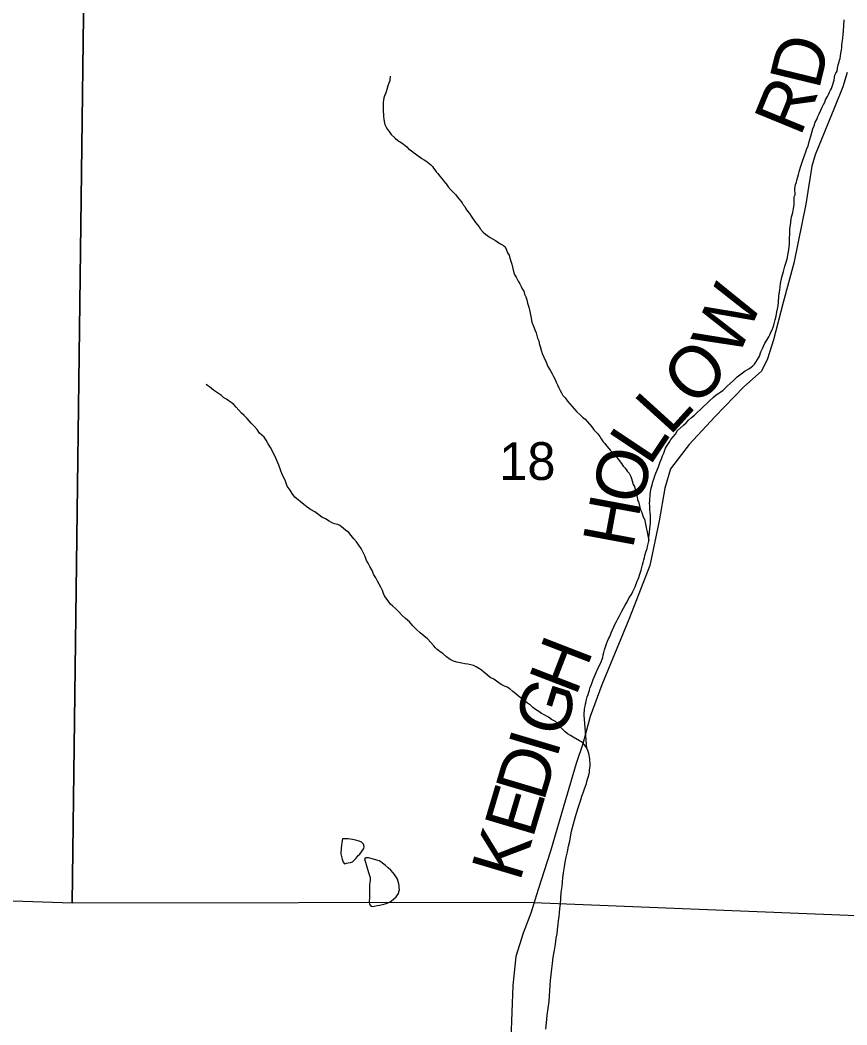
# Model space of a CAD drawing. Extents: x -14196 to 143, y -6096 to 28.
# Drawn here: x 59.148 to 60.064, y 19.711 to 20.825 of the extents above; entities that cross this region are included whole.
import ezdxf

# ---------------------------------------------------------------- set-up
doc = ezdxf.new("R2010")
doc.units = 0
for name, color, linetype in [('GM_X_Corporation', 7, 'Continuous'), ('GM_X_County_Road', 7, 'Continuous'), ('GM_X_County_Road_Text', 7, 'Continuous'), ('GM_X_Minor_Lake', 7, 'Continuous'), ('GM_X_Minor_River', 7, 'Continuous'), ('GM_X_Section_Text', 7, 'Continuous')]:
    doc.layers.add(name, color=color, linetype=linetype)

msp = doc.modelspace()

# ---------------------------------------------------------------- linework, layer by layer
at = {"layer": 'GM_X_Corporation'}
for points in [[(59.2185, 20.859), (59.2056, 19.8463), (58.2013, 19.8806), (58.2134, 20.8668)], [(60.2211, 20.8437), (60.2036, 19.8271), (59.7077, 19.847), (59.2056, 19.8463), (59.2185, 20.859)]]:
    msp.add_lwpolyline(points, close=True, dxfattribs=at)
at = {"layer": 'GM_X_County_Road'}
msp.add_lwpolyline([(60.0646, 20.767), (60.0597, 20.7513), (60.0504, 20.7283), (60.0293, 20.6757), (60.0255, 20.6634), (60.0189, 20.621), (60.0054, 20.5557), (59.9936, 20.5121), (59.9829, 20.4707), (59.9762, 20.4497), (59.9697, 20.4362), (59.95, 20.4186), (59.9178, 20.3855), (59.8893, 20.3547), (59.8687, 20.328), (59.8624, 20.3065), (59.8561, 20.2703), (59.846, 20.2206), (59.8235, 20.1626), (59.7928, 20.0885), (59.7796, 20.0532), (59.7716, 20.0229), (59.7642, 20.0011), (59.7523, 19.9609), (59.7359, 19.9042), (59.7222, 19.8617), (59.7141, 19.8352), (59.7055, 19.8133), (59.6974, 19.7873), (59.6941, 19.7553), (59.6906, 19.6666)], dxfattribs=at)
at = {"layer": 'GM_X_Minor_Lake'}
for points in [[(59.5048, 19.916), (59.5038, 19.9076), (59.5038, 19.9057), (59.5035, 19.9034), (59.5035, 19.9011), (59.5039, 19.8981), (59.5047, 19.8951), (59.5059, 19.892), (59.5074, 19.8902), (59.5097, 19.8906), (59.5116, 19.891), (59.5142, 19.8914), (59.5161, 19.8922), (59.5184, 19.8945), (59.5203, 19.8964), (59.5225, 19.8991), (59.5244, 19.9006), (59.5289, 19.9071), (59.5292, 19.9094), (59.5284, 19.9117), (59.5261, 19.9139), (59.5235, 19.915), (59.5212, 19.9158), (59.5181, 19.9165), (59.5162, 19.9169), (59.5136, 19.9172), (59.5113, 19.9176), (59.5079, 19.9179), (59.506, 19.9179), (59.5052, 19.9179), (59.5048, 19.916)], [(59.5048, 19.916), (59.5038, 19.9076), (59.5038, 19.9057), (59.5035, 19.9034), (59.5035, 19.9011), (59.5039, 19.8981), (59.5047, 19.8951), (59.5059, 19.892), (59.5074, 19.8902), (59.5097, 19.8906), (59.5116, 19.891), (59.5142, 19.8914), (59.5161, 19.8922), (59.5184, 19.8945), (59.5203, 19.8964), (59.5225, 19.8991)], [(59.5225, 19.8991), (59.5244, 19.9006), (59.5289, 19.9071), (59.5292, 19.9094), (59.5284, 19.9117), (59.5261, 19.9139), (59.5235, 19.915), (59.5212, 19.9158), (59.5181, 19.9165), (59.5162, 19.9169), (59.5136, 19.9172), (59.5113, 19.9176), (59.5079, 19.9179), (59.506, 19.9179), (59.5052, 19.9179), (59.5048, 19.916)], [(59.5566, 19.847), (59.5592, 19.8485), (59.5622, 19.8512), (59.5648, 19.8535), (59.5671, 19.857), (59.5678, 19.8589), (59.5682, 19.8615), (59.5681, 19.8634), (59.5681, 19.8653), (59.5677, 19.868), (59.5661, 19.8729), (59.565, 19.8748), (59.563, 19.8782), (59.5615, 19.8801), (59.5588, 19.8831), (59.5557, 19.8857), (59.5526, 19.8884), (59.5496, 19.8906), (59.5477, 19.8921), (59.5458, 19.8932), (59.5431, 19.894), (59.5397, 19.8951), (59.5339, 19.8965), (59.5313, 19.8965), (59.5294, 19.8957)], [(59.5294, 19.8957), (59.5341, 19.8806), (59.5353, 19.8772), (59.5357, 19.8749), (59.5358, 19.8718), (59.5354, 19.8692), (59.535, 19.8673), (59.5351, 19.8654), (59.5351, 19.8627), (59.5351, 19.8604), (59.5352, 19.8585), (59.5352, 19.8551), (59.5352, 19.8532), (59.5352, 19.8513), (59.5349, 19.8494), (59.5349, 19.8475), (59.5353, 19.8452), (59.5369, 19.8426), (59.5403, 19.843), (59.5437, 19.8438), (59.5463, 19.8442), (59.5494, 19.845), (59.5524, 19.8458), (59.5547, 19.8466), (59.5566, 19.847), (59.5592, 19.8485), (59.5622, 19.8512), (59.5648, 19.8535), (59.5671, 19.857), (59.5678, 19.8589), (59.5682, 19.8615), (59.5681, 19.8634), (59.5681, 19.8653), (59.5677, 19.868), (59.5661, 19.8729), (59.565, 19.8748), (59.563, 19.8782), (59.5615, 19.8801), (59.5588, 19.8831), (59.5557, 19.8857), (59.5526, 19.8884), (59.5496, 19.8906), (59.5477, 19.8921), (59.5458, 19.8932), (59.5431, 19.894), (59.5397, 19.8951), (59.5339, 19.8965), (59.5313, 19.8965), (59.5294, 19.8957)], [(59.5294, 19.8957), (59.5341, 19.8806), (59.5353, 19.8772), (59.5357, 19.8749), (59.5358, 19.8718), (59.5354, 19.8692), (59.535, 19.8673), (59.5351, 19.8654), (59.5351, 19.8627), (59.5351, 19.8604), (59.5352, 19.8585), (59.5352, 19.8551), (59.5352, 19.8532), (59.5352, 19.8513), (59.5349, 19.8494), (59.5349, 19.8475), (59.5353, 19.8452), (59.5369, 19.8426), (59.5403, 19.843), (59.5437, 19.8438), (59.5463, 19.8442), (59.5494, 19.845), (59.5524, 19.8458), (59.5547, 19.8466), (59.5566, 19.847)]]:
    msp.add_lwpolyline(points, dxfattribs=at)
at = {"layer": 'GM_X_Minor_River'}
for points in [[(60.0293, 20.7119), (60.0308, 20.7149), (60.0319, 20.7184), (60.0334, 20.7214), (60.0353, 20.7252), (60.0367, 20.7287), (60.0382, 20.7317), (60.0397, 20.7344), (60.0404, 20.7367), (60.0416, 20.7386), (60.0427, 20.7405), (60.0438, 20.7428), (60.0449, 20.7455), (60.046, 20.7474), (60.0471, 20.7493), (60.0479, 20.7516), (60.0486, 20.7539), (60.0493, 20.7565), (60.0501, 20.7588), (60.0504, 20.7615), (60.0511, 20.7642), (60.0522, 20.7665), (60.0534, 20.7687), (60.0537, 20.7718), (60.0541, 20.7737), (60.0548, 20.7756), (60.0559, 20.779), (60.0562, 20.7809), (60.057, 20.7828), (60.0573, 20.7855), (60.0577, 20.7886), (60.0584, 20.792), (60.0587, 20.795), (60.0587, 20.7977), (60.0591, 20.8003), (60.0594, 20.8026), (60.0598, 20.8053), (60.0601, 20.8095), (60.0604, 20.8129), (60.0614, 20.8255)], [(59.558, 20.763), (59.5582, 20.7625), (59.5578, 20.7602), (59.5575, 20.7579), (59.5567, 20.7553), (59.5556, 20.7522), (59.5545, 20.7484), (59.5531, 20.7446), (59.5516, 20.7412), (59.5509, 20.7389), (59.5505, 20.7366), (59.5502, 20.7343), (59.5502, 20.7309), (59.5502, 20.7271), (59.5503, 20.7237), (59.5507, 20.721), (59.5507, 20.7184), (59.5511, 20.7153), (59.5515, 20.7127), (59.552, 20.7096), (59.5535, 20.7066), (59.5551, 20.704), (59.557, 20.7017), (59.5593, 20.6983), (59.5635, 20.6945), (59.5666, 20.6919), (59.5701, 20.6897), (59.5727, 20.6878), (59.5747, 20.6863), (59.5766, 20.6848), (59.5785, 20.6825), (59.5812, 20.6807), (59.5835, 20.6788), (59.5862, 20.6769), (59.5931, 20.6717), (59.5957, 20.6702), (59.5988, 20.6683), (59.6011, 20.6664), (59.603, 20.6649), (59.6049, 20.6631), (59.6061, 20.6612), (59.6076, 20.6593), (59.6092, 20.657), (59.6107, 20.6551), (59.6127, 20.6525), (59.6154, 20.6495), (59.6177, 20.6468), (59.62, 20.6438), (59.6223, 20.6404), (59.6254, 20.637), (59.6281, 20.634), (59.6308, 20.6314), (59.6327, 20.6288), (59.6346, 20.6269), (59.6362, 20.6246), (59.6377, 20.6227), (59.6389, 20.6205), (59.6408, 20.6186), (59.642, 20.6159), (59.6439, 20.6133), (59.6458, 20.6107), (59.6478, 20.608), (59.6493, 20.6058), (59.6512, 20.6031), (59.6528, 20.6008), (59.6547, 20.5982), (59.6566, 20.5959), (59.6582, 20.5933), (59.6613, 20.5903), (59.6636, 20.588), (59.6662, 20.5862), (59.6689, 20.5843), (59.6716, 20.5828), (59.6747, 20.5809), (59.6773, 20.5791), (59.6804, 20.5772), (59.6835, 20.5753), (59.6854, 20.5738), (59.6866, 20.5712), (59.6881, 20.5674), (59.69, 20.5648), (59.6908, 20.5613), (59.6916, 20.5579), (59.6928, 20.5545), (59.6952, 20.545), (59.6964, 20.5424), (59.6976, 20.5401), (59.6987, 20.5382), (59.6999, 20.536), (59.7018, 20.5329), (59.7034, 20.5299), (59.7045, 20.5273), (59.7061, 20.5246), (59.7069, 20.5216), (59.7084, 20.5186), (59.7096, 20.5152), (59.7104, 20.5114), (59.7116, 20.5072), (59.7128, 20.5023)], [(59.8624, 20.3484), (59.8631, 20.3507), (59.8642, 20.3526), (59.8657, 20.3549), (59.8672, 20.3572), (59.8691, 20.3602), (59.8717, 20.3633), (59.8743, 20.3664), (59.8766, 20.3702), (59.88, 20.3733), (59.883, 20.3763), (59.886, 20.379), (59.8886, 20.3817), (59.892, 20.3848), (59.8954, 20.3875), (59.9055, 20.3971), (59.9089, 20.4002), (59.9119, 20.4032), (59.9164, 20.4071), (59.9194, 20.4098), (59.9224, 20.4117), (59.9247, 20.4133), (59.9273, 20.4152), (59.9292, 20.4171), (59.9314, 20.4194), (59.9348, 20.4225), (59.9386, 20.4259), (59.9427, 20.4298), (59.9472, 20.4332), (59.9517, 20.4363), (59.9555, 20.4386), (59.9581, 20.4406), (59.96, 20.4421), (59.9619, 20.444), (59.9634, 20.4459), (59.9653, 20.449), (59.9675, 20.4528), (59.969, 20.4574), (59.9712, 20.462), (59.9734, 20.467), (59.9756, 20.4704), (59.9779, 20.4742), (59.979, 20.4765), (59.9801, 20.4792), (59.9816, 20.4819), (59.9827, 20.4849), (59.9838, 20.4887), (59.9849, 20.4929), (59.986, 20.4971), (59.9867, 20.5017), (59.9877, 20.5066), (59.9884, 20.5119), (59.9887, 20.5196), (59.9898, 20.526), (59.9908, 20.5333), (59.9923, 20.5401), (59.9941, 20.5466), (59.9956, 20.5523), (59.997, 20.5569), (59.9985, 20.5622), (59.9992, 20.5668), (59.9999, 20.5706), (60.0002, 20.574), (60.0006, 20.5774), (60.0005, 20.5809), (60.0012, 20.5904), (60.0011, 20.5942), (60.0018, 20.598), (60.0022, 20.6014), (60.0025, 20.6044), (60.0029, 20.6071), (60.0036, 20.6094), (60.0043, 20.6121), (60.005, 20.6162), (60.0058, 20.6204), (60.0057, 20.6239), (60.0057, 20.6269), (60.006, 20.6292), (60.0068, 20.6315), (60.0067, 20.6383), (60.0074, 20.6429), (60.0085, 20.6455), (60.0088, 20.6478), (60.0099, 20.6513), (60.0107, 20.6539), (60.0114, 20.657), (60.0121, 20.6596), (60.0128, 20.6623), (60.0139, 20.6657), (60.015, 20.6688), (60.0176, 20.6764), (60.0187, 20.6791), (60.0198, 20.6829), (60.0213, 20.6856), (60.022, 20.689), (60.0231, 20.6928), (60.0242, 20.6966), (60.0253, 20.7008), (60.0264, 20.7046), (60.0279, 20.7081), (60.0293, 20.7119)], [(59.7128, 20.5023), (59.714, 20.4966), (59.7152, 20.4905), (59.7168, 20.486), (59.7184, 20.4818), (59.7199, 20.4784), (59.7207, 20.4758), (59.7215, 20.4727), (59.7227, 20.4697), (59.7231, 20.4667), (59.7243, 20.4633), (59.7255, 20.4595), (59.7267, 20.4557), (59.7282, 20.4515), (59.731, 20.4462), (59.7329, 20.4413), (59.7352, 20.4371), (59.7372, 20.4337), (59.7391, 20.43), (59.7411, 20.4269), (59.7422, 20.4239), (59.7434, 20.4209), (59.745, 20.4175), (59.7465, 20.4148), (59.7481, 20.4122), (59.7496, 20.4092), (59.7516, 20.4069), (59.7531, 20.405), (59.7546, 20.4028), (59.757, 20.3997), (59.7597, 20.3971), (59.7623, 20.3941), (59.765, 20.3911), (59.7681, 20.3881), (59.7712, 20.3851), (59.7743, 20.3828), (59.7816, 20.3742), (59.7839, 20.3711), (59.7862, 20.3685), (59.7881, 20.3666), (59.7904, 20.3636), (59.792, 20.361), (59.7943, 20.3579), (59.7955, 20.3561), (59.7982, 20.353), (59.8005, 20.3504), (59.802, 20.3485), (59.8055, 20.3451), (59.8066, 20.3433), (59.8086, 20.3414), (59.8101, 20.3395), (59.812, 20.3372), (59.8143, 20.3338), (59.8163, 20.3308), (59.8182, 20.3289), (59.8197, 20.327), (59.8209, 20.3252), (59.8228, 20.3229), (59.8248, 20.3195), (59.8256, 20.3172), (59.8263, 20.3146), (59.8275, 20.3104), (59.8287, 20.3081), (59.8295, 20.3051), (59.8303, 20.3025), (59.8311, 20.2994), (59.8319, 20.2964), (59.8323, 20.2937), (59.8335, 20.2903), (59.8343, 20.2869), (59.8351, 20.2839), (59.8359, 20.2816), (59.837, 20.2793), (59.8382, 20.2759), (59.839, 20.2737), (59.8398, 20.2721), (59.8447, 20.2485)], [(59.5871, 20.1498), (59.5833, 20.1539), (59.5794, 20.1581), (59.5752, 20.1618), (59.5714, 20.1652), (59.5679, 20.169), (59.5644, 20.1728), (59.561, 20.1758), (59.5583, 20.178), (59.5564, 20.1806), (59.5548, 20.1829), (59.5533, 20.1848), (59.5517, 20.1871), (59.5506, 20.1897), (59.5494, 20.1931), (59.5478, 20.1965), (59.5459, 20.1999), (59.544, 20.2033), (59.542, 20.2071), (59.5401, 20.2105), (59.5381, 20.215), (59.5354, 20.2196), (59.5335, 20.2234), (59.5319, 20.2264), (59.5303, 20.2305), (59.528, 20.2351), (59.5257, 20.2396), (59.5233, 20.2434), (59.5206, 20.2468), (59.5179, 20.2502), (59.5149, 20.2539), (59.5122, 20.2573), (59.5087, 20.26), (59.5064, 20.2618), (59.5041, 20.2637), (59.5022, 20.2652), (59.4999, 20.2663), (59.4965, 20.267), (59.493, 20.2685), (59.4904, 20.27), (59.4862, 20.2723), (59.4823, 20.2741), (59.4789, 20.2767), (59.4747, 20.2801), (59.4697, 20.2827), (59.4662, 20.2854), (59.4624, 20.2884), (59.4524, 20.2966), (59.4494, 20.3004), (59.447, 20.3042), (59.4439, 20.3087), (59.4416, 20.3151), (59.4385, 20.3215), (59.4345, 20.3318), (59.4314, 20.3397), (59.4283, 20.3461), (59.4252, 20.3514), (59.4229, 20.3556), (59.4205, 20.3597), (59.4182, 20.3628), (59.4159, 20.365), (59.4132, 20.3673), (59.4105, 20.3714), (59.4074, 20.3752), (59.404, 20.3786), (59.3994, 20.3835), (59.3963, 20.3868), (59.3932, 20.3895), (59.3901, 20.3929), (59.3874, 20.3963), (59.3847, 20.3993), (59.3817, 20.4015), (59.3794, 20.403), (59.3767, 20.4049), (59.3736, 20.4067), (59.371, 20.409), (59.3667, 20.412), (59.3621, 20.415), (59.3579, 20.4187), (59.3556, 20.4202), (59.3541, 20.4214)], [(59.7761, 20.0179), (59.7729, 20.0548), (59.7732, 20.0575), (59.7736, 20.0598), (59.7735, 20.0617), (59.7743, 20.0647), (59.7746, 20.0674), (59.7753, 20.0701), (59.7757, 20.072), (59.7764, 20.075), (59.7775, 20.0777), (59.7782, 20.0803), (59.779, 20.0826), (59.7797, 20.0853), (59.7808, 20.088), (59.7819, 20.091), (59.783, 20.0945), (59.7886, 20.1071), (59.7904, 20.1105), (59.7919, 20.1139), (59.793, 20.117), (59.7937, 20.1189), (59.7941, 20.1216), (59.7948, 20.1242), (59.7955, 20.1273), (59.7966, 20.1307), (59.7977, 20.1338), (59.7988, 20.1368), (59.7999, 20.1395), (59.8011, 20.1414), (59.8022, 20.1437), (59.8029, 20.146), (59.8044, 20.1494), (59.8059, 20.1528), (59.8073, 20.1559), (59.8088, 20.1586), (59.8103, 20.1616), (59.8118, 20.1643), (59.8133, 20.167), (59.8148, 20.17), (59.8166, 20.1735), (59.8185, 20.1769), (59.8207, 20.1804), (59.8229, 20.1853), (59.8256, 20.1884), (59.827, 20.1918), (59.8285, 20.1949), (59.8296, 20.1972), (59.8304, 20.1991), (59.8311, 20.201), (59.8318, 20.2033), (59.833, 20.2056), (59.8337, 20.2075), (59.8344, 20.2098), (59.8352, 20.2121), (59.8363, 20.2155), (59.837, 20.2185), (59.8377, 20.2216), (59.8384, 20.2239), (59.8392, 20.2269), (59.8399, 20.2296), (59.8402, 20.2319), (59.841, 20.2342), (59.8417, 20.2364), (59.8428, 20.2395), (59.8432, 20.2418), (59.8446, 20.2475), (59.8449, 20.2517), (59.8453, 20.2543), (59.8456, 20.2578), (59.846, 20.2612), (59.8463, 20.2646), (59.8466, 20.268), (59.8466, 20.2715), (59.8466, 20.276), (59.8461, 20.2794), (59.8457, 20.2825), (59.8457, 20.2847), (59.8457, 20.287), (59.8456, 20.2897), (59.846, 20.2924), (59.8459, 20.295), (59.8463, 20.2973), (59.8463, 20.2992), (59.8466, 20.3019), (59.847, 20.3049), (59.8477, 20.3076), (59.8484, 20.3102), (59.8491, 20.3133), (59.8502, 20.3163), (59.8513, 20.3201), (59.8524, 20.3232), (59.8536, 20.3255), (59.8543, 20.3274), (59.8554, 20.3301), (59.8561, 20.3324), (59.8569, 20.3346), (59.8587, 20.3388), (59.8598, 20.3423), (59.8613, 20.3453), (59.8624, 20.3484)], [(59.7462, 19.8406), (59.7469, 19.8455), (59.7475, 19.8581), (59.7485, 19.8649), (59.7489, 19.8699), (59.7496, 19.8745), (59.7502, 19.8802), (59.7513, 19.8866), (59.752, 19.892), (59.7531, 19.8973), (59.7545, 19.9034), (59.7556, 19.9095), (59.757, 19.9152), (59.7581, 19.9201), (59.7592, 19.9262), (59.7603, 19.9304), (59.7614, 19.9342), (59.7625, 19.9384), (59.7636, 19.9426), (59.765, 19.9472), (59.7665, 19.9522), (59.7679, 19.9564), (59.7694, 19.9609), (59.7705, 19.9651), (59.772, 19.9686), (59.7731, 19.972), (59.7745, 19.9762), (59.7757, 19.9789), (59.776, 19.9811), (59.7767, 19.9838), (59.7775, 19.9861), (59.7786, 19.9899), (59.7789, 19.9918), (59.7789, 19.9937), (59.7792, 19.9964), (59.7796, 19.9983), (59.7796, 20.0017), (59.7795, 20.0044), (59.7795, 20.0063), (59.7791, 20.0082), (59.7787, 20.0104), (59.7783, 20.0123), (59.7775, 20.0146), (59.7767, 20.0169), (59.7752, 20.0195), (59.7736, 20.0218), (59.7709, 20.0248), (59.7679, 20.0263), (59.761, 20.0304), (59.7579, 20.0323), (59.7545, 20.0341), (59.7518, 20.0368), (59.7483, 20.0401), (59.7453, 20.0435), (59.7414, 20.0477), (59.7368, 20.0499), (59.7334, 20.0525), (59.7296, 20.0548), (59.7257, 20.0566), (59.7227, 20.0589), (59.7192, 20.0611), (59.7162, 20.0634), (59.7135, 20.066), (59.7104, 20.0682), (59.7077, 20.0705), (59.7047, 20.0727), (59.7004, 20.0757), (59.6974, 20.0784), (59.6939, 20.081), (59.6908, 20.084), (59.6878, 20.0859), (59.6847, 20.087), (59.6817, 20.0885), (59.679, 20.0903), (59.6759, 20.0926), (59.6729, 20.0948), (59.669, 20.0967), (59.666, 20.0993), (59.6618, 20.1023), (59.6591, 20.1046), (59.6572, 20.1061), (59.6552, 20.1072), (59.6533, 20.1083), (59.6503, 20.1098), (59.6476, 20.1105), (59.6442, 20.1113), (59.6408, 20.1116), (59.6373, 20.1123), (59.632, 20.1134), (59.6282, 20.1145), (59.6244, 20.1164), (59.6205, 20.1194), (59.6167, 20.1228), (59.6129, 20.1254), (59.6102, 20.1276), (59.6083, 20.1295), (59.6063, 20.1318), (59.5994, 20.1393), (59.5952, 20.1427), (59.5914, 20.1461), (59.5871, 20.1498)], [(59.7307, 19.7067), (59.7313, 19.7139), (59.732, 19.7223), (59.7331, 19.7299), (59.7341, 19.7375), (59.7348, 19.7436), (59.7351, 19.7493), (59.7354, 19.7554), (59.7357, 19.7607), (59.7364, 19.7671), (59.7371, 19.7736), (59.7378, 19.7797), (59.7388, 19.7866), (59.7403, 19.7942), (59.7413, 19.801), (59.742, 19.8075), (59.7431, 19.8124), (59.7434, 19.8174), (59.7441, 19.8227), (59.7448, 19.8273), (59.7455, 19.8311), (59.7458, 19.8356), (59.7462, 19.8406)]]:
    msp.add_lwpolyline(points, dxfattribs=at)

# ---------------------------------------------------------------- texts
at = {"layer": 'GM_X_County_Road_Text'}
for s, rotation, p in [('D', 76.3346, (60.0332, 20.7469)), ('R', 67.7065, (60.0126, 20.695)), ('W', 66.1846, (59.9426, 20.4487)), ('O', 46.3498, (59.8962, 20.3947)), ('L', 47.7678, (59.8679, 20.3635)), ('L', 56.298, (59.8457, 20.3299)), ('O', 76.2783, (59.836, 20.2861)), ('H', 79.4902, (59.827, 20.2378)), ('H', 68.8547, (59.7638, 20.0747)), ('G', 72.5408, (59.7491, 20.0279)), ('I', 73.3426, (59.7425, 20.0058)), ('D', 73.3983, (59.7282, 19.9579)), ('E', 73.3916, (59.716, 19.9171)), ('K', 73.3901, (59.7017, 19.8692))]:
    msp.add_text(s, height=0.0568, rotation=rotation, dxfattribs=at).set_placement(p)
at = {"layer": 'GM_X_Section_Text'}
msp.add_text('18', height=0.04186, rotation=0, dxfattribs=at).set_placement((59.679, 20.3155))

doc.saveas('drawing.dxf')
